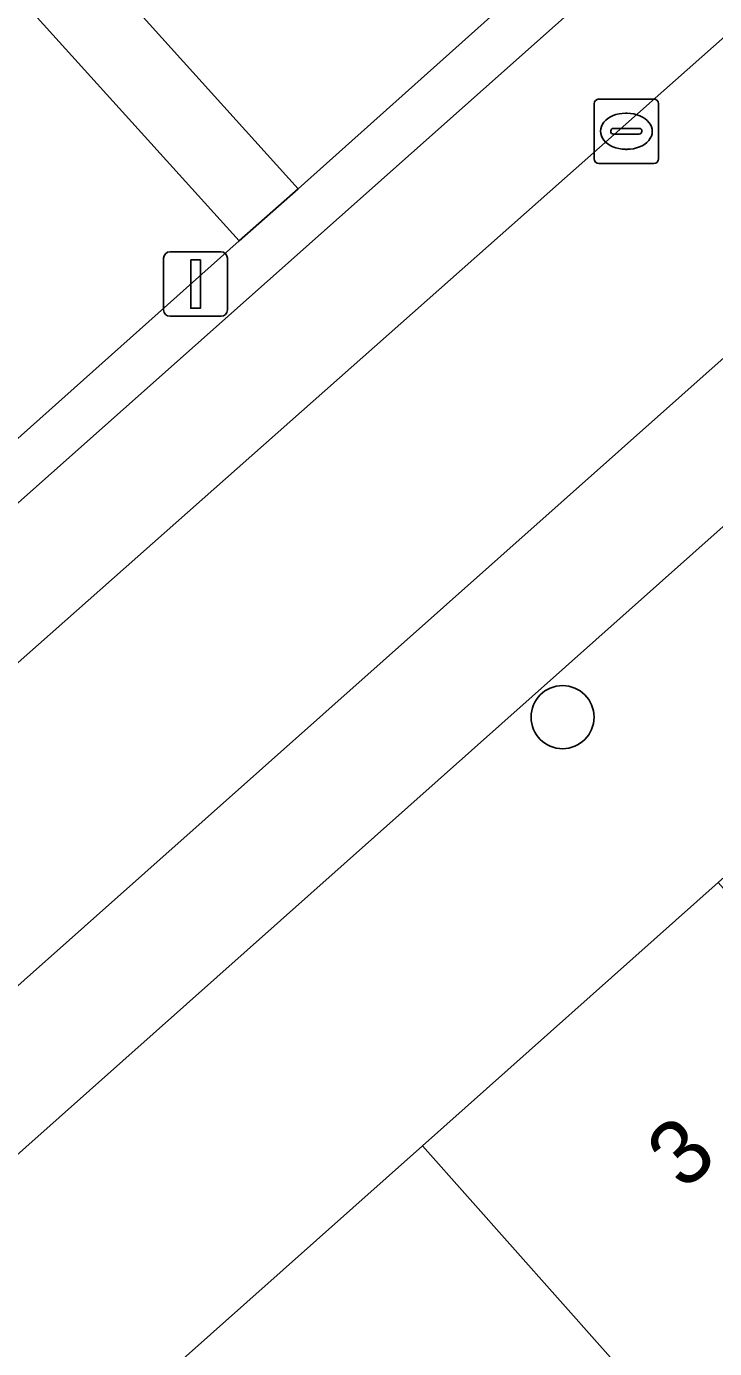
# Model space of a CAD drawing. Extents: x 159960 to 160866, y 382700 to 383354.
# Drawn here: x 160519.51 to 160530.18, y 383018.43 to 383038.93 of the extents above; entities that cross this region are included whole.
import ezdxf

# ---------------------------------------------------------------- set-up
doc = ezdxf.new("R2010")
doc.units = 0
for name, color, linetype in [('IMGEO_Boom', 7, 'Continuous'), ('IMGEO_Groenvoorziening', 7, 'Continuous'), ('IMGEO_Kolk', 7, 'Continuous'), ('IMGEO_Lichtmast', 7, 'Continuous'), ('IMGEO_Pand', 7, 'Continuous'), ('IMGEO_Pand_nummerreeks', 7, 'Continuous'), ('IMGEO_Parkeervlak_open', 7, 'Continuous'), ('IMGEO_Rijbaan_lokaal_open', 7, 'Continuous'), ('IMGEO_Voetpad_open', 7, 'Continuous')]:
    doc.layers.add(name, color=color, linetype=linetype)

msp = doc.modelspace()

# ---------------------------------------------------------------- linework, layer by layer
at = {"layer": 'IMGEO_Boom'}
msp.add_circle((160527.826, 383028.218), 0.489, dxfattribs=at)
at = {"layer": 'IMGEO_Groenvoorziening'}
for points in [[(160526.706, 383039.078), (160524.254, 383041.791), (160521.272, 383039.124), (160523.725, 383036.41)], [(160518.99, 383032.198), (160522.812, 383035.601), (160518.545, 383040.319), (160514.81, 383036.989), (160515.275, 383036.456)]]:
    msp.add_lwpolyline(points, close=True, dxfattribs=at)
at = {"layer": 'IMGEO_Kolk'}
for p, q in [((160528.315, 383036.876), (160528.315, 383037.728)), ((160528.39, 383037.802), (160529.242, 383037.802)), ((160529.316, 383037.728), (160529.316, 383036.876)), ((160528.803, 383037.582), (160528.828, 383037.582)), ((160528.574, 383037.296), (160528.574, 383037.308)), ((160529.012, 383037.259), (160528.614, 383037.259)), ((160528.617, 383037.345), (160529.015, 383037.345)), ((160529.058, 383037.308), (160529.058, 383037.296)), ((160528.826, 383037.022), (160528.801, 383037.022)), ((160529.242, 383036.802), (160528.39, 383036.802))]:
    msp.add_line(p, q, dxfattribs=at)
for points in [[(160528.315, 383036.876), (160528.315, 383037.728)], [(160528.39, 383037.802), (160529.242, 383037.802)], [(160529.316, 383037.728), (160529.316, 383036.876)], [(160529.242, 383036.802), (160528.39, 383036.802)]]:
    msp.add_lwpolyline(points, dxfattribs=at)
for centre, radius, start, end in [((160528.392, 383037.726), 0.0765, 91.552, 178.448), ((160528.392, 383037.726), 0.0765, 91.552, 178.448), ((160529.24, 383037.726), 0.0765, 1.552, 88.448), ((160529.24, 383037.726), 0.0765, 1.552, 88.448), ((160528.614, 383037.305), 0.0403, 85.8775, 175.7526), ((160528.611, 383037.295), 0.0366, 178.938, 274.7102), ((160529.015, 383037.302), 0.043, 264.8664, 352.4533), ((160529.019, 383037.307), 0.0386, 1.7309, 96.639), ((160528.392, 383036.878), 0.0765, 181.552, 268.448), ((160528.392, 383036.878), 0.0765, 181.552, 268.448), ((160529.24, 383036.878), 0.0765, 271.552, 358.448), ((160529.24, 383036.878), 0.0765, 271.552, 358.448)]:
    msp.add_arc(centre, radius, start, end, dxfattribs=at)
for centre, major_axis, ratio, start_param, end_param in [((160528.802, 383037.302), (-0.387, 0.002), 0.722429, 4.712389, 7.853982), ((160528.827, 383037.302), (-0.39, 0.002), 0.717154, 1.570796, 4.712389)]:
    msp.add_ellipse(centre, major_axis=major_axis, ratio=ratio, start_param=start_param, end_param=end_param, dxfattribs=at)
at = {"layer": 'IMGEO_Lichtmast'}
for p, q in [((160521.738, 383035.433), (160522.528, 383035.433)), ((160522.528, 383035.433), (160521.738, 383035.433)), ((160521.638, 383034.533), (160521.638, 383035.333)), ((160521.638, 383035.333), (160521.638, 383034.533)), ((160522.628, 383035.333), (160522.628, 383034.533)), ((160522.628, 383034.533), (160522.628, 383035.333)), ((160522.528, 383034.433), (160521.738, 383034.433)), ((160521.738, 383034.433), (160522.528, 383034.433))]:
    msp.add_line(p, q, dxfattribs=at)
msp.add_lwpolyline([(160522.058, 383035.308), (160522.208, 383035.308), (160522.208, 383034.558), (160522.058, 383034.558), (160522.058, 383035.308)], dxfattribs=at)
for centre, start, end in [((160521.738, 383035.333), 90, 180), ((160521.738, 383035.333), 90, 180), ((160522.528, 383035.333), 0, 90), ((160522.528, 383035.333), 360, 90), ((160521.738, 383034.533), 180, 270), ((160521.738, 383034.533), 180, 270), ((160522.528, 383034.533), 270, 0), ((160522.528, 383034.533), 270, 0)]:
    msp.add_arc(centre, 0.1, start, end, dxfattribs=at)
at = {"layer": 'IMGEO_Pand'}
for points in [[(160530.241, 383025.653), (160525.653, 383021.57), (160533.332, 383012.929), (160535.544, 383014.898), (160535.319, 383015.151), (160537.695, 383017.266)], [(160525.653, 383021.57), (160520.205, 383016.722), (160520.085, 383016.857), (160519.924, 383016.714), (160524.231, 383011.869), (160525.281, 383012.802), (160528.747, 383008.902), (160529.303, 383009.396), (160529.06, 383009.669), (160531.363, 383011.718), (160531.631, 383011.416), (160533.332, 383012.929)]]:
    msp.add_lwpolyline(points, close=True, dxfattribs=at)
at = {"layer": 'IMGEO_Parkeervlak_open'}
for points in [[(160513.301, 383023.684), (160533.07, 383041.19), (160532.669, 383041.084), (160532.263, 383041.05), (160530.617, 383041.161)], [(160529.896, 383040.889), (160514.169, 383026.917)], [(160533.374, 383036.497), (160515.772, 383020.855), (160507.385, 383013.336), (160506.959, 383012.954), (160464.19, 382975.008), (160465.501, 382973.516), (160495.273, 383000), (160495.719, 383000.397), (160500, 383004.175), (160506.219, 383009.663)], [(160506.219, 383009.663), (160508.67, 383011.861), (160516.594, 383018.967), (160517.049, 383019.372), (160532.292, 383032.931)]]:
    msp.add_lwpolyline(points, dxfattribs=at)
at = {"layer": 'IMGEO_Rijbaan_lokaal_open'}
msp.add_lwpolyline([(160535.945, 383037.991), (160534.432, 383041.689), (160533.968, 383041.559), (160533.857, 383041.513), (160533.07, 383041.19), (160513.301, 383023.684), (160514.675, 383022.129), (160515.772, 383020.855), (160533.374, 383036.497)], dxfattribs=at)
at = {"layer": 'IMGEO_Voetpad_open'}
for points in [[(160505.58, 383027.472), (160506.93, 383028.69), (160515.275, 383036.456), (160514.81, 383036.989), (160518.545, 383040.319), (160522.812, 383035.601), (160523.725, 383036.41), (160521.272, 383039.124), (160524.254, 383041.791), (160527.865, 383045.02), (160528.189, 383045.31), (160529.25, 383046.25), (160528.98, 383046.59), (160532.081, 383049.37)], [(160529.648, 383041.711), (160526.706, 383039.078), (160523.725, 383036.41), (160522.812, 383035.601), (160518.99, 383032.198), (160513.412, 383027.23)], [(160514.169, 383026.917), (160529.896, 383040.889)], [(160503.134, 383000.632), (160507.318, 383004.348), (160511.574, 383008.127), (160511, 383008.773), (160515.352, 383012.646), (160519.924, 383016.714), (160520.085, 383016.857), (160520.205, 383016.722), (160525.653, 383021.57), (160530.241, 383025.653), (160534.784, 383029.696), (160534.919, 383029.816), (160534.814, 383029.933), (160532.292, 383032.931), (160517.049, 383019.372), (160516.594, 383018.967), (160508.67, 383011.861), (160506.219, 383009.663), (160500, 383004.175)]]:
    msp.add_lwpolyline(points, dxfattribs=at)

# ---------------------------------------------------------------- texts
at = {"layer": 'IMGEO_Pand_nummerreeks'}
msp.add_text('3', height=1, rotation=41.3401, dxfattribs=at).set_placement((160529.704, 383020.859))

doc.saveas('drawing.dxf')
